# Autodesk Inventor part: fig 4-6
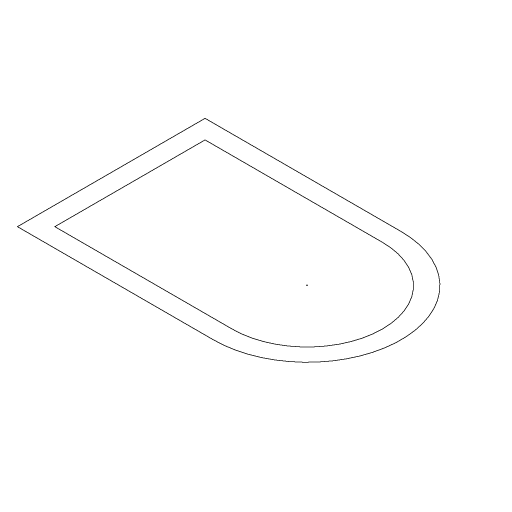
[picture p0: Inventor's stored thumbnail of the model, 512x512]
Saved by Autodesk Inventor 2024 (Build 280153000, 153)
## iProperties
Created: 2005-02
Part Number: fig 4-6
Document SubType Name: Modeling
Designer: CADCIM
Manufacturer: Standard
Standards Organization: Custom
Density: 1 g/cm^3
Material: Generic
Appearance: Default
Author: CADCIM
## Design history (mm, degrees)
sketch "Sketch1"
  geometry: L1 (12.963, 23.563)-(-25.99, 23.563); L2 (-25.99, 23.563)-(-25.99, -13.729); L3 (-25.99, -13.729)-(12.963, -13.729); L4 (-22.275, 19.848)-(12.963, 19.848); L5 (12.963, -10.014)-(-22.275, -10.014); L6 (-22.275, -10.014)-(-22.275, 19.848); A1 r 18.646 centre (12.963, 4.917) between (12.963, -13.729) and (12.963, 23.563); A2 r 14.931 centre (12.963, 4.917) between (12.963, -10.014) and (12.963, 19.848)
  constraints: 12 end point, 4 point on circle, 2 centre point, 2 parallel, 2 perpendicular, 2 tangent, 1 horizontal, 4 other
